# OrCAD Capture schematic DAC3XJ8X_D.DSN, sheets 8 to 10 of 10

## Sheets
8 SHEET 7 - FMC CONN: size B; title: OUTPUT
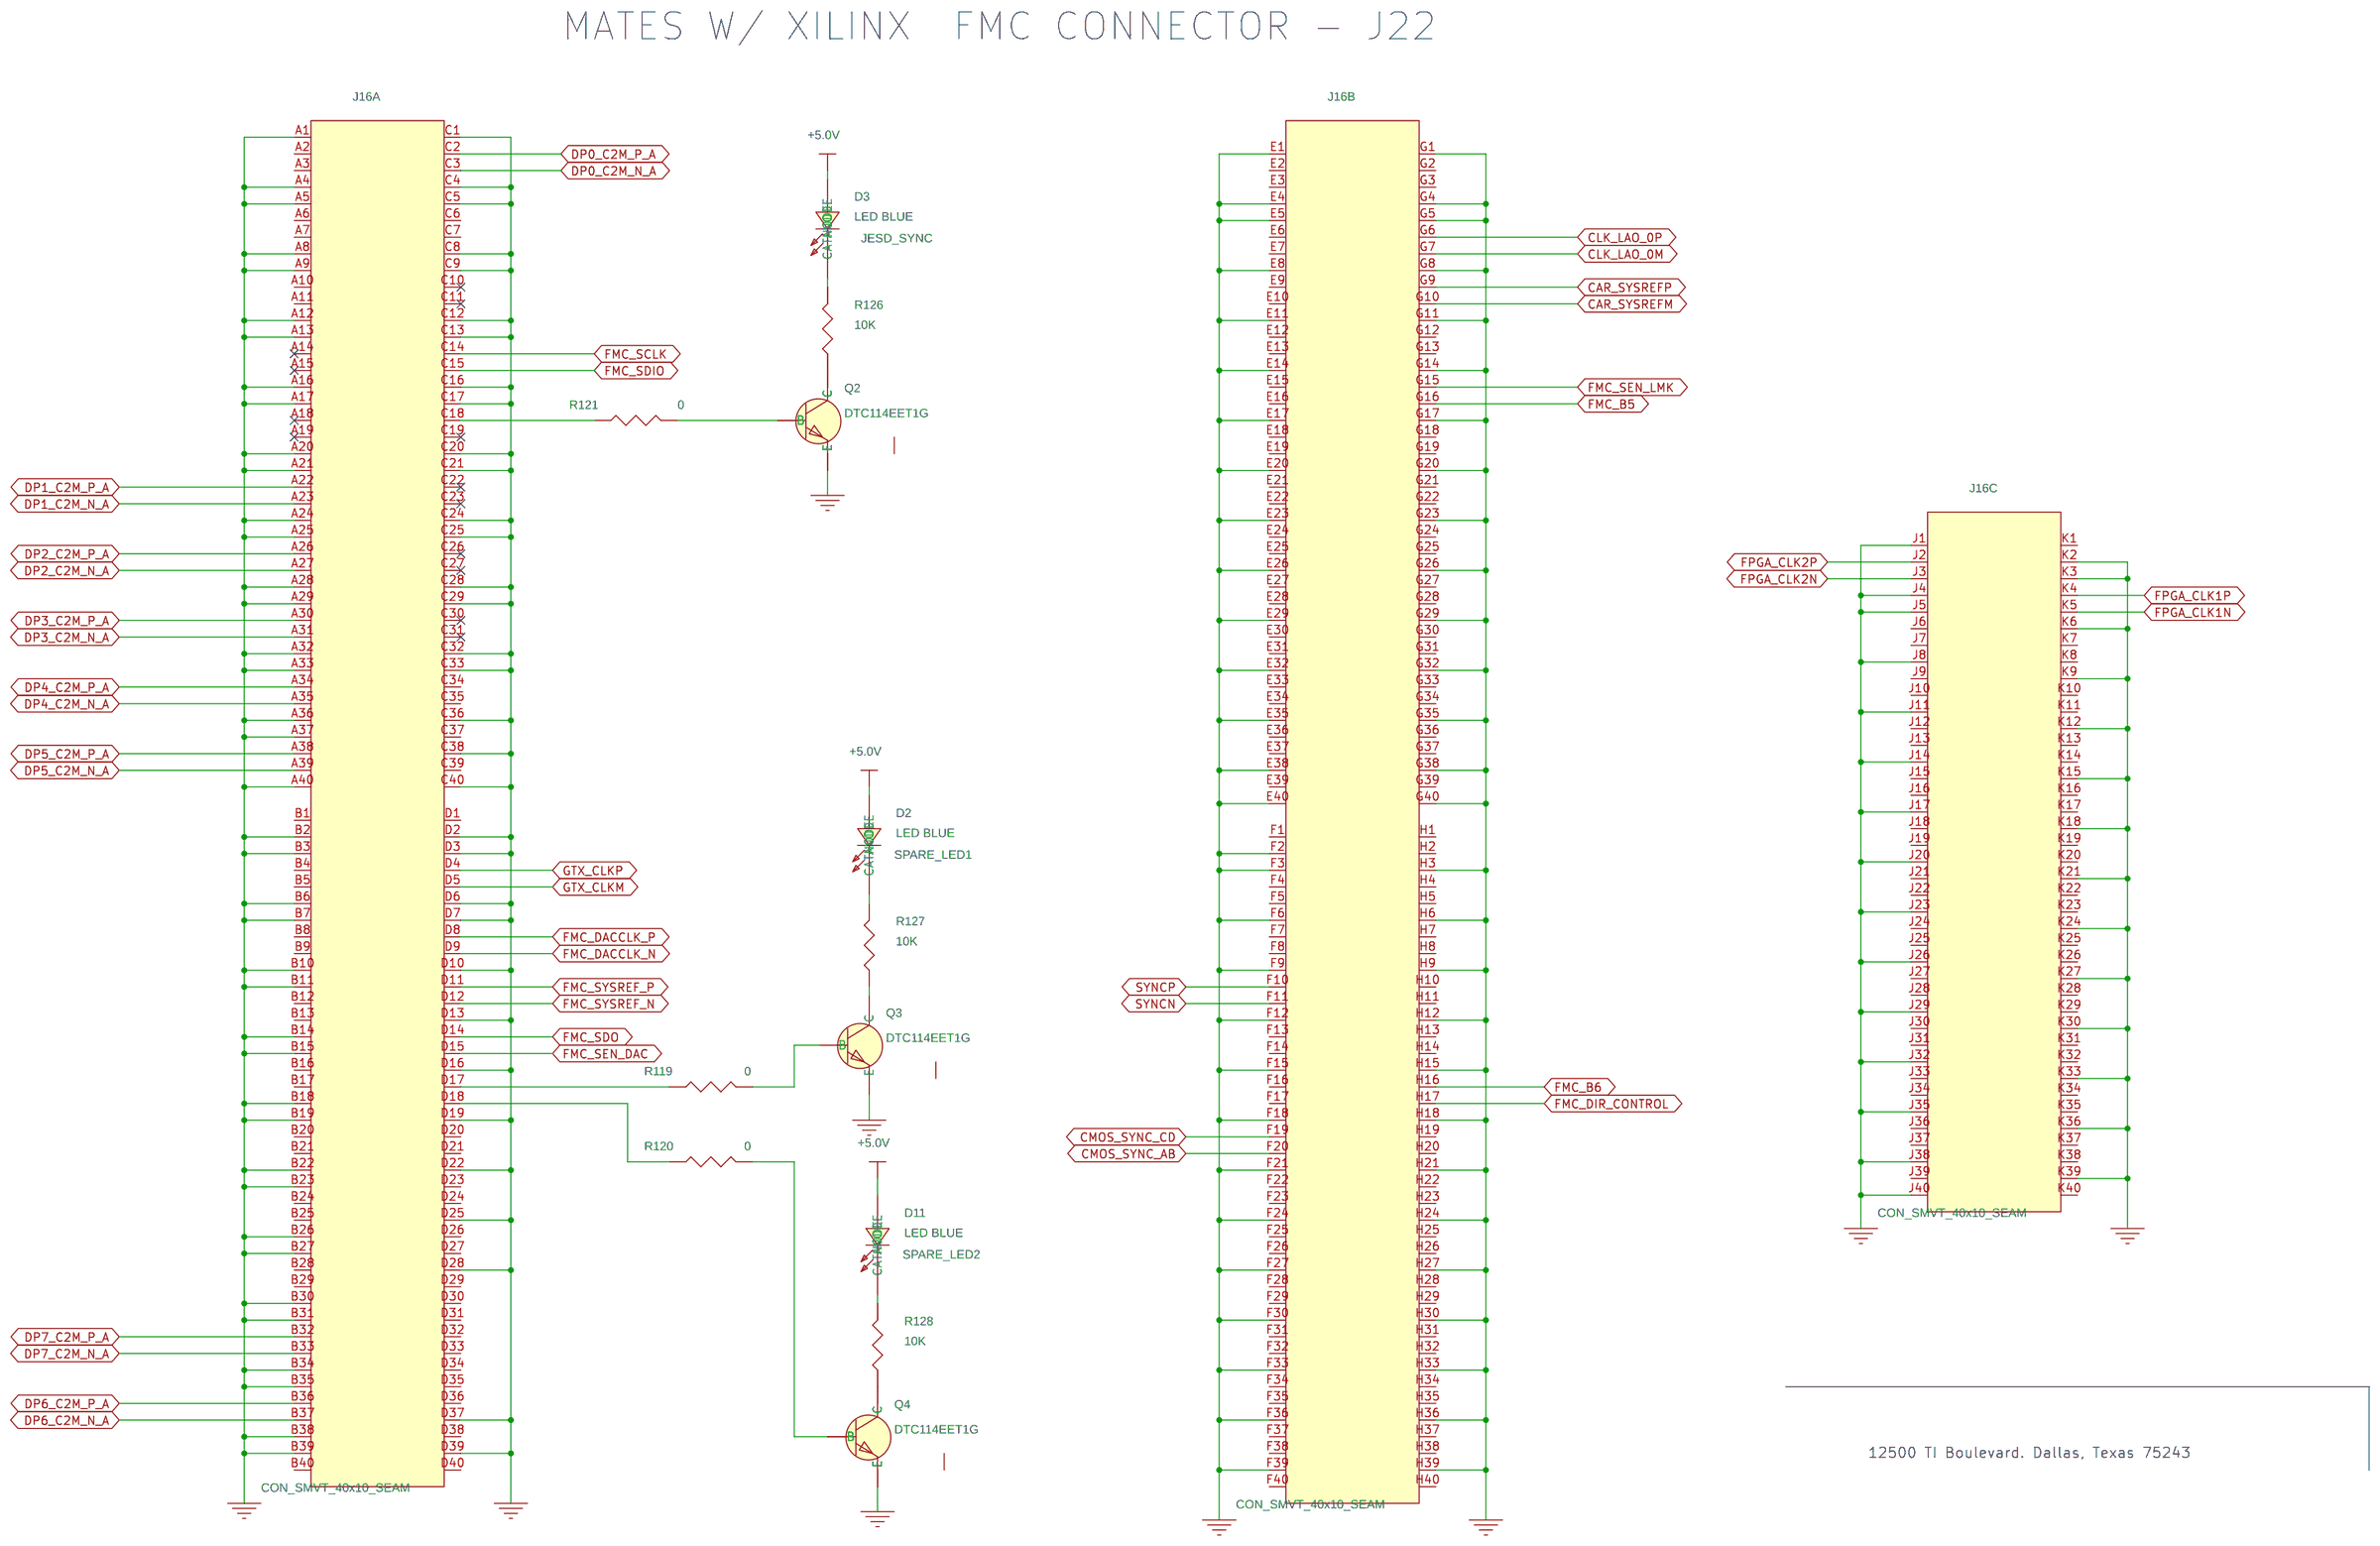
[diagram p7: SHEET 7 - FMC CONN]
9 SHEET 9 - MAIN POWER SUPPLIES: size B; title: MAIN POWER
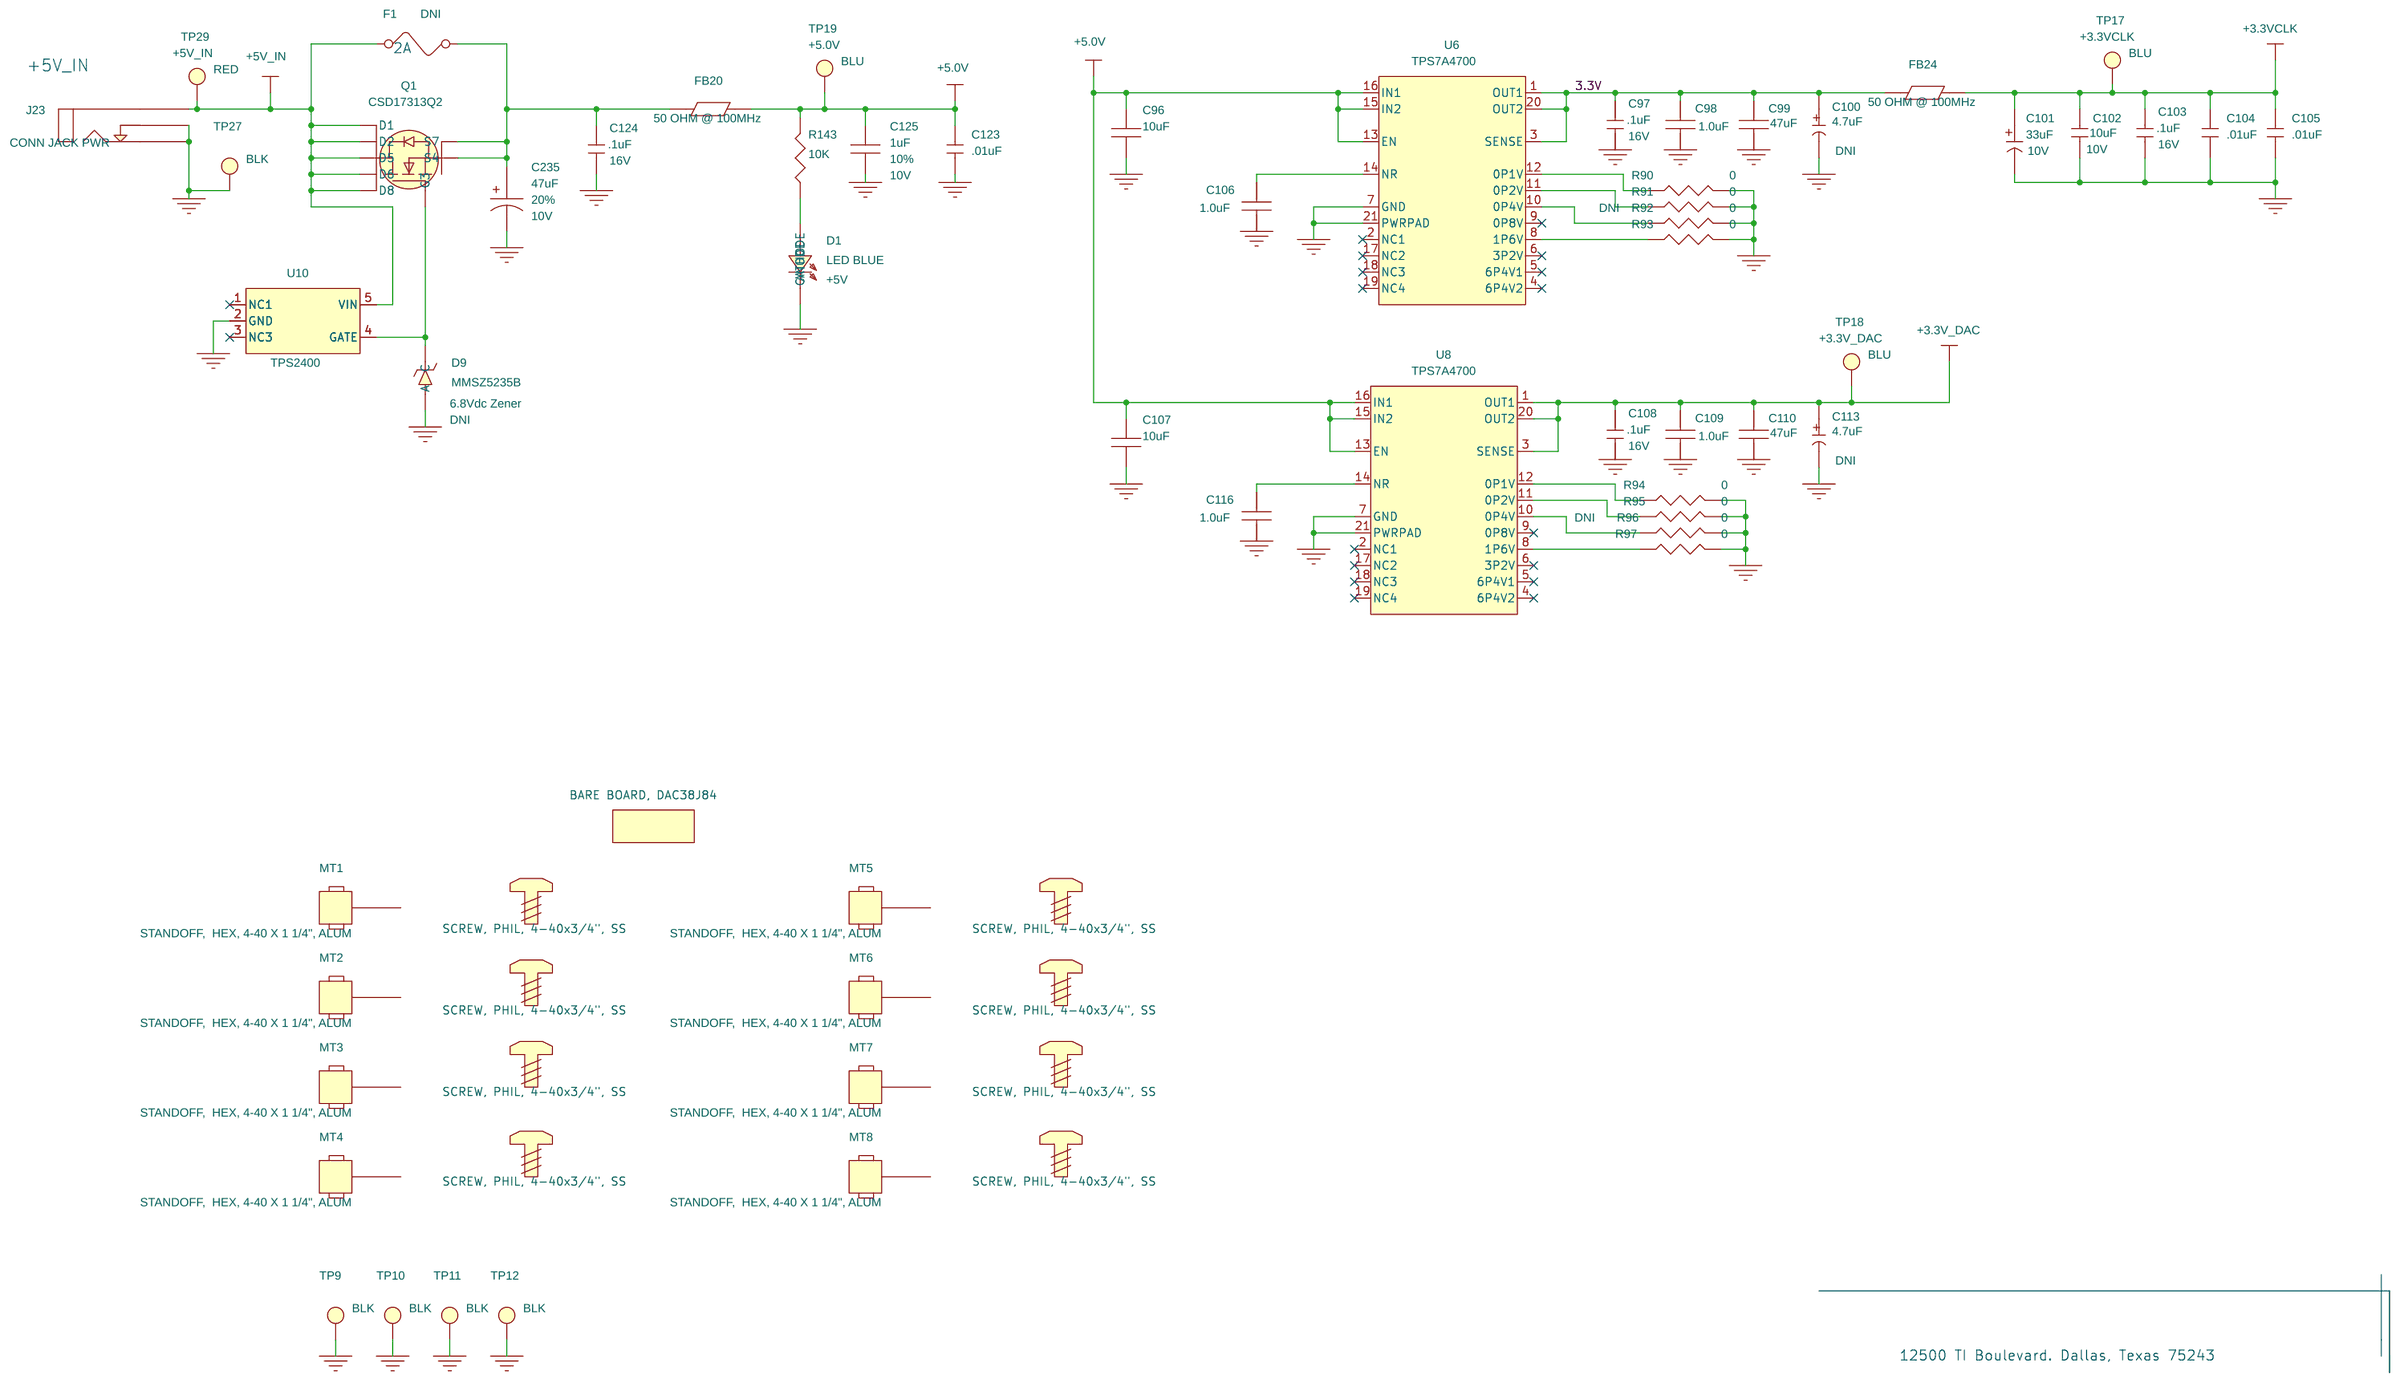
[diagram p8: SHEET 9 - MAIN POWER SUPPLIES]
10 SHEET 8 - USB I/F: size B; title: USB INTERFACE
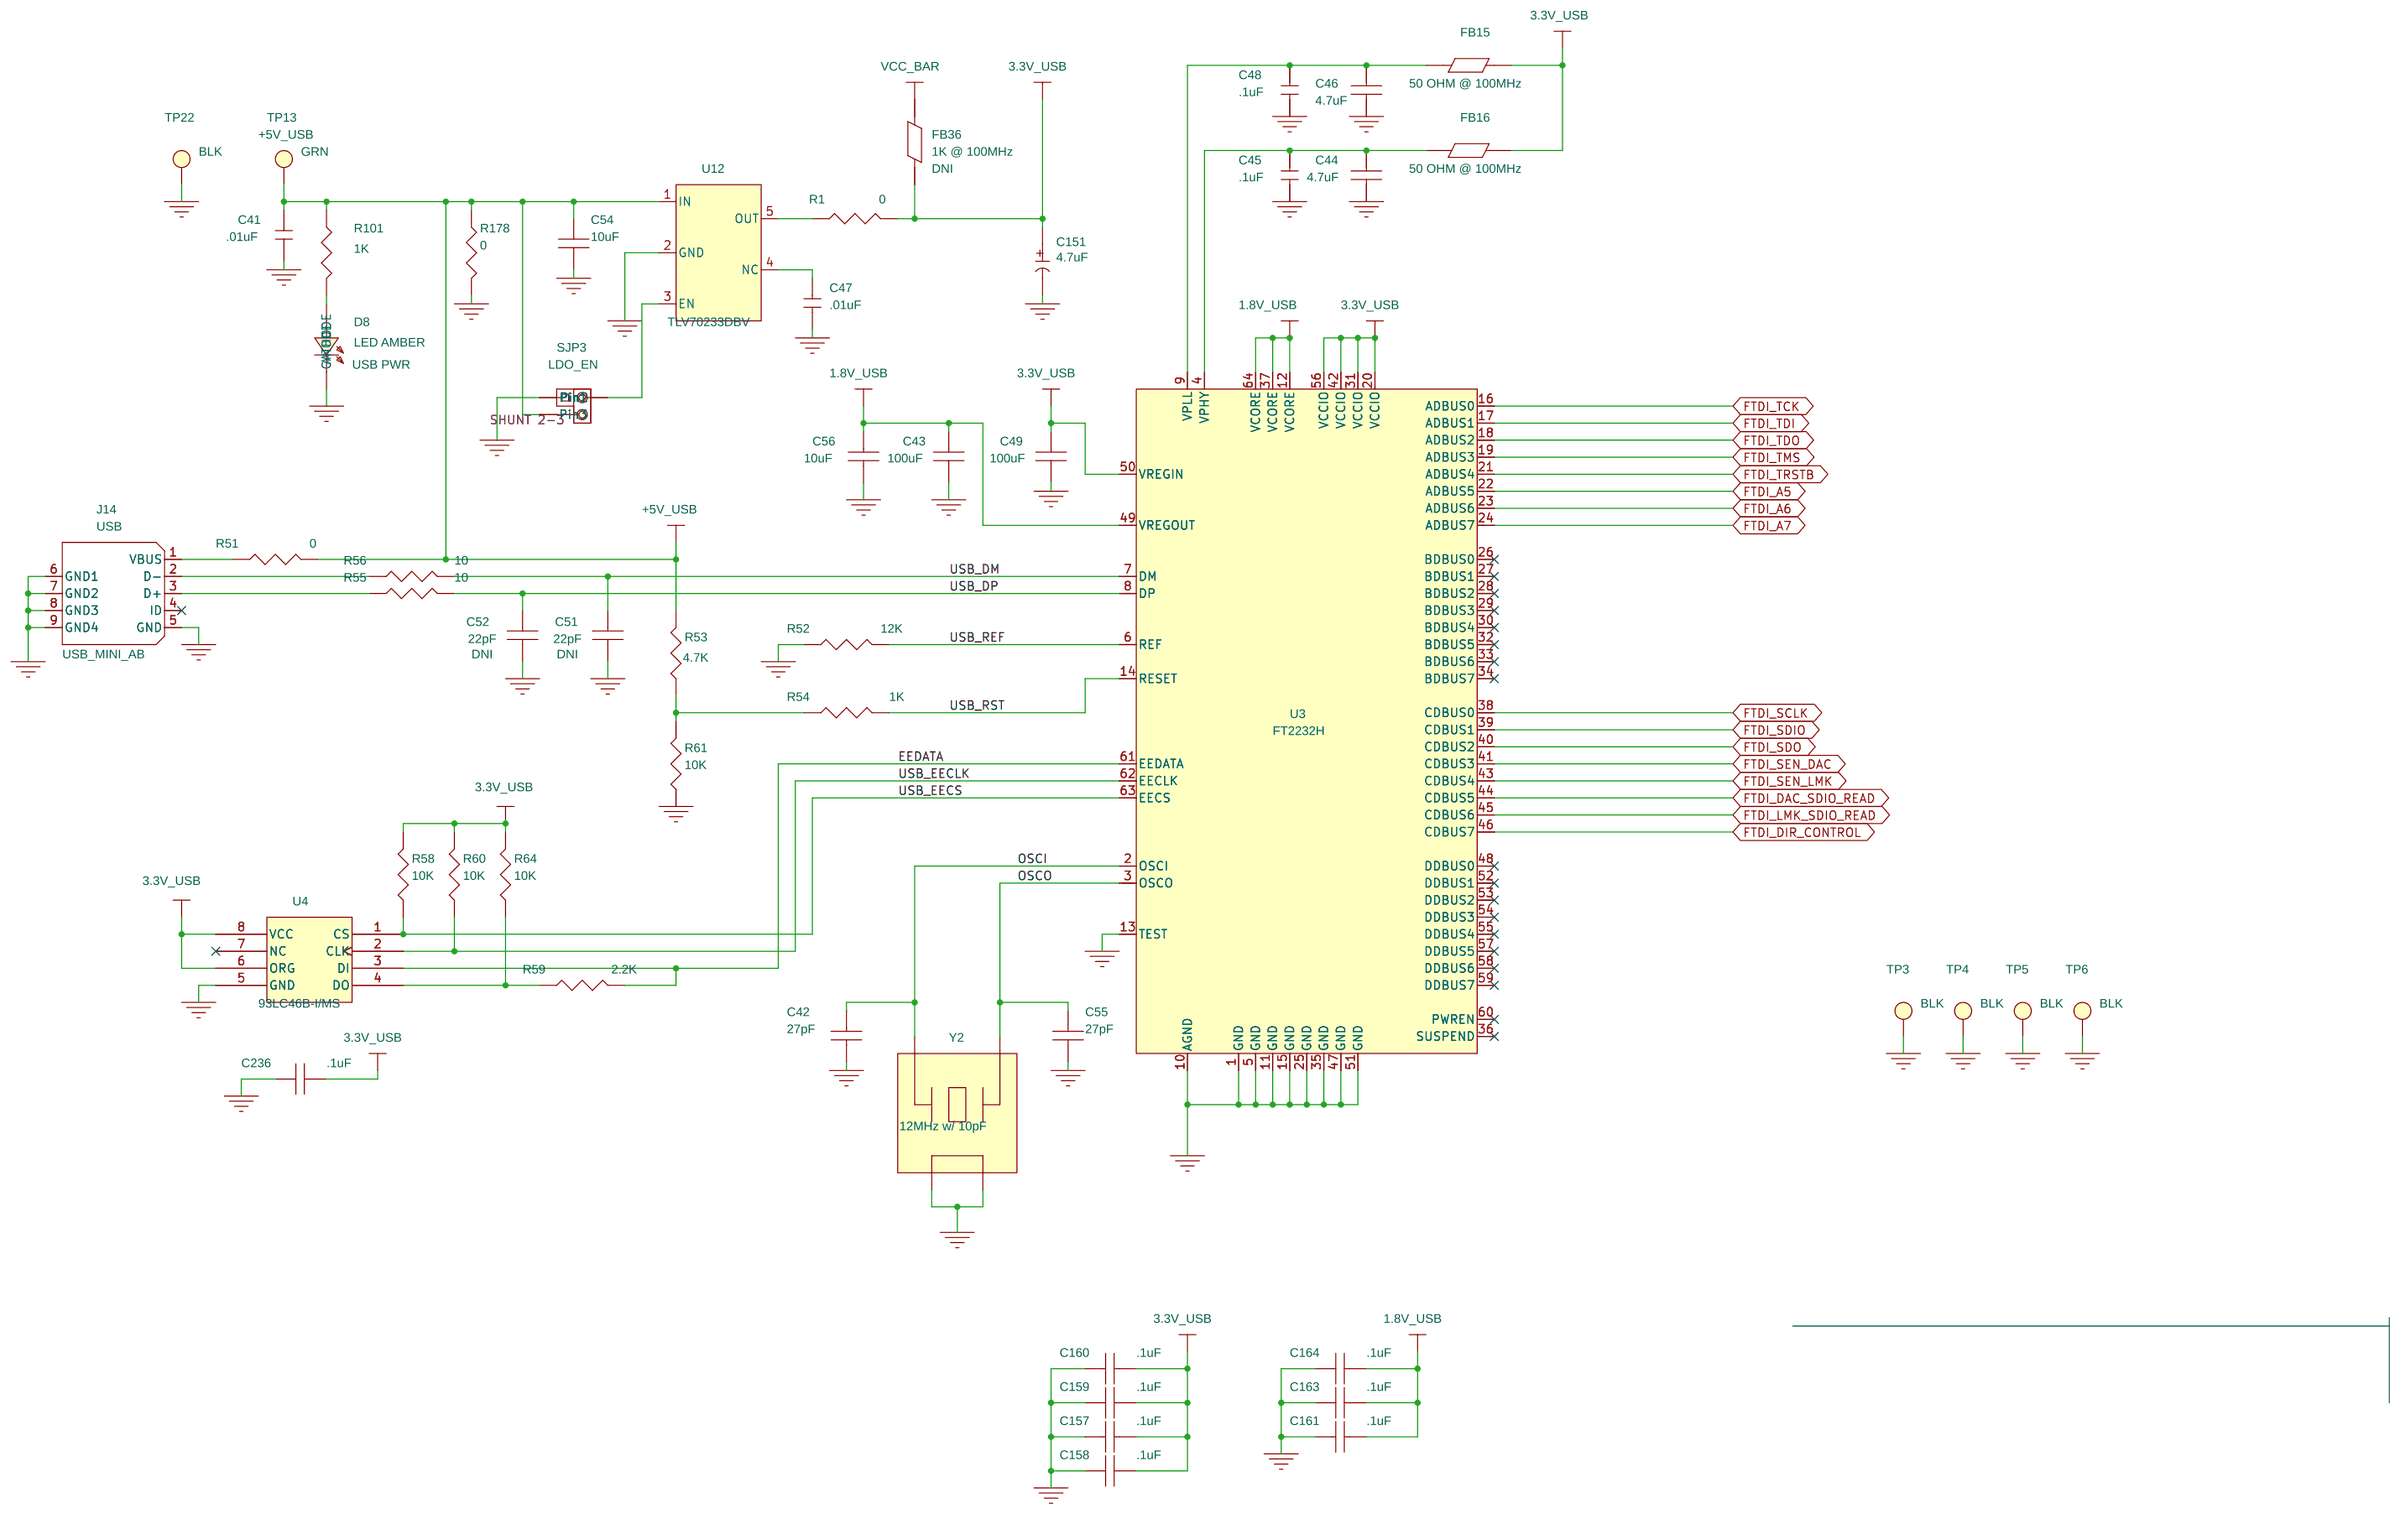
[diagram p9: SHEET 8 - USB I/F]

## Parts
sheet SHEET 7 - FMC CONN
D2  LED BLUE  [LED_1206]
D3  LED BLUE  [LED_1206]
D11  LED BLUE  [LED_1206]
J16  CON_SMVT_40x10_SEAM  [CON_SMVT_40x10_ASP-134487-01]  (sections A,B,C)
Q2  DTC114EET1G  [SOT_416_3_63x31]
Q3  DTC114EET1G  [SOT_416_3_63x31]
Q4  DTC114EET1G  [SOT_416_3_63x31]
R119  0  [0603]
R120  0  [0603]
R121  0  [0603]
R126  10K  [0603]
R127  10K  [0603]
R128  10K  [0603]
sheet SHEET 8 - USB I/F
C41  .01uF  [0603]
C42  27pF  [0402]
C43  100uF  [1206]
C44  4.7uF  [0603]
C45  .1uF  [0402]
C46  4.7uF  [0603]
C47  .01uF  [0603]
C48  .1uF  [0402]
C49  100uF  [1206]
C51  22pF  [0402]
C52  22pF  [0402]
C54  10uF  [1206]
C55  27pF  [0402]
C56  10uF  [1206]
C151  4.7uF  [TANT_B]
C157  .1uF  [0402]
C158  .1uF  [0402]
C159  .1uF  [0402]
C160  .1uF  [0402]
C161  .1uF  [0402]
C163  .1uF  [0402]
C164  .1uF  [0402]
C236  .1uF  [0402]
D8  LED AMBER  [LED_1206]
FB15  50 OHM @ 100MHz  [1206]
FB16  50 OHM @ 100MHz  [1206]
FB36  1K @ 100MHz  [0603]
J14  USB_MINI_AB  [CON_SMRT_USBMNE20_F]
R1  0  [0805]
R51  0  [0603]
R52  12K  [0402]
R53  4.7K  [0402]
R54  1K  [0402]
R55  10  [0402]
R56  10  [0402]
R58  10K  [0402]
R59  2.2K  [0402]
R60  10K  [0402]
R61  10K  [0402]
R64  10K  [0402]
R101  1K  [0402]
R178  0  [0402]
SJP3  JUMPER_L_0603_SMT  [JUMPER_SMD_L_0603]
TP3  BLK  [TP_THVT_100_RND_GND]
TP4  BLK  [TP_THVT_100_RND_GND]
TP5  BLK  [TP_THVT_100_RND_GND]
TP6  BLK  [TP_THVT_100_RND_GND]
TP13  GRN  [TP_THVT_100_RND]
TP22  BLK  [TP_THVT_100_RND_GND]
U3  FT2232H  [LQFP_64_402x402_20]
U4  93LC46B-I/MS  [MSOP_8_118X118_26]
U12  TLV70233DBV  [SOT_5_118X67_57]
Y2  12MHz w/ 10pF  [XTAL_4_SM_130X102]
Z_SH-J9  SHUNT-JUMPER-0603
sheet SHEET 9 - MAIN POWER SUPPLIES
C96  10uF  [0805]
C97  .1uF  [0402]
C98  1.0uF  [0603]
C99  47uF  [1206]
C100  4.7uF  [TANT_B]
C101  33uF  [TANT_B]
C102  10uF  [0805]
C103  .1uF  [0402]
C104  .01uF  [0603]
C105  .01uF  [0603]
C106  1.0uF  [0603]
C107  10uF  [0805]
C108  .1uF  [0402]
C109  1.0uF  [0603]
C110  47uF  [1206]
C113  4.7uF  [TANT_B]
C116  1.0uF  [0603]
C123  .01uF  [0603]
C124  .1uF  [0402]
C125  1uF  [0402]
C235  47uF  [tant_b]
D1  LED BLUE  [LED_1206]
D9  MMSZ5235B  [DIODE_SM_SOD_123]
F1  FUSE 2.0A 63V FAST  [1206]
FB20  50 OHM @ 100MHz  [1206]
FB24  50 OHM @ 100MHz  [1206]
J23  CONN JACK PWR  [CON_RAPC722_JACK_THVT_3]
MT1  STANDOFF,  HEX, 4-40 X 1 1/4", ALUM  [MFG125_PLATED]
MT2  STANDOFF,  HEX, 4-40 X 1 1/4", ALUM  [MFG125_PLATED]
MT3  STANDOFF,  HEX, 4-40 X 1 1/4", ALUM  [MFG125_PLATED]
MT4  STANDOFF,  HEX, 4-40 X 1 1/4", ALUM  [MFG125_PLATED]
MT5  STANDOFF,  HEX, 4-40 X 1 1/4", ALUM  [MFG125_PLATED]
MT6  STANDOFF,  HEX, 4-40 X 1 1/4", ALUM  [MFG125_PLATED]
MT7  STANDOFF,  HEX, 4-40 X 1 1/4", ALUM  [MFG125_PLATED]
MT8  STANDOFF,  HEX, 4-40 X 1 1/4", ALUM  [MFG125_PLATED]
Q1  CSD17313Q2  [mosfet_8_2mmx2mm_0p65]
R90  0  [0402]
R91  0  [0402]
R92  0  [0402]
R93  0  [0402]
R94  0  [0402]
R95  0  [0402]
R96  0  [0402]
R97  0  [0402]
R143  10K  [0603]
TP9  BLK  [TP_THVT_100_RND_GND]
TP10  BLK  [TP_THVT_100_RND_GND]
TP11  BLK  [TP_THVT_100_RND_GND]
TP12  BLK  [TP_THVT_100_RND_GND]
TP17  BLU  [TP_THVT_100_RND]
TP18  BLU  [TP_THVT_100_RND]
TP19  BLU  [TP_THVT_100_RND]
TP27  BLK  [TP_THVT_100_RND_GND]
TP29  RED  [TP_THVT_100_RND]
U6  TPS7A4700  [qfn20_rgw_p65pitch]
U8  TPS7A4700  [qfn20_rgw_p65pitch]
U10  TPS2400  [DBV5]
Z_BOARD1  BARE BOARD, DAC38J84
Z_SCREW1  SCREW, PHIL, 4-40x3/4", SS
Z_SCREW2  SCREW, PHIL, 4-40x3/4", SS
Z_SCREW3  SCREW, PHIL, 4-40x3/4", SS
Z_SCREW4  SCREW, PHIL, 4-40x3/4", SS
Z_SCREW5  SCREW, PHIL, 4-40x3/4", SS
Z_SCREW6  SCREW, PHIL, 4-40x3/4", SS
Z_SCREW7  SCREW, PHIL, 4-40x3/4", SS
Z_SCREW8  SCREW, PHIL, 4-40x3/4", SS

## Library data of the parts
D2 = LED: CLASS: DISCRETE; Mfr_Name: LITE ON; Mfr_Part_Number: LTST-C150TBKT; TI_SILKTEXT: SPARE_LED1
D3 = LED: CLASS: DISCRETE; Mfr_Name: LITE ON; Mfr_Part_Number: LTST-C150TBKT; TI_SILKTEXT: JESD_SYNC
D11 = LED: CLASS: DISCRETE; Mfr_Name: LITE ON; Mfr_Part_Number: LTST-C150TBKT; TI_SILKTEXT: SPARE_LED2
J16 = CON_SMVT_40X10_ASP-134487-01: Mfr_Part_Number: SEAM-40-02.0-S-10-2-A-K-TR
Q2-Q4 = MMBT2222A: Mfr_Name: ON Semiconductor
R119-R121 = Res_0603_Zero_H
R126-R128 = R: Mfr_Name: PANASONIC; Mfr_Part_Number: ERJ-3EKF1002V; TOL: 1%; VOLTAGE: 1/10W
C41 C47 C104 C105 C123 = CAP_0603_0.01uF: Mfr_Part_Number: C0603C103K5RACTU
C42 C55 = CAP_NP: GROUP: NOT INSTALLED; Mfr_Name: YAGEO; Mfr_Part_Number: CC0402JRNPO9BN270; PART_NUMBER: GRM1885C2A330JA01D; TOL: 5%; VOLTAGE: 50V
C43 C49 = CAP_1206: Mfr_Name: KEMET; Mfr_Part_Number: C1206C107M9PACTU
C44 C46 = CAP_NP_0: Mfr_Name: Kemet; Mfr_Part_Number: C0603C475K8PACTU; TOL: 10%; VOLTAGE: 10V
C45 C48 C97 C103 C108 C124 = CAP0603: Mfr_Name: MURATA; Mfr_Part_Number: GRM155R71C104KA88D; TOL: 10%; Voltage: 16V
C51 C52 = CAP_NP: Mfr_Name: AVX; Mfr_Part_Number: 04025A220KAT2A_DNI; Note: DNI; TOL: 10%; VOLTAGE: 50V
C54 C56 = CAP_NP_1: CLASS: DISCRETE; Mfr_Name: MURATA; Mfr_Part_Number: GRM31CR61E106KA12L; TOL: 10%; VOLTAGE: 16V
C151 = CAP_TANT_B_4.7uF_10V: Mfr_Part_Number: TAJB475K010RNJ
C157-C161 C163 C164 C236 = CAPACITOR_NP_1: Mfr_Name: MURATA; Mfr_Part_Number: GRM155R71C104KA88D; TOL: 10%; Voltage: 16V
D8 = LED_AMBER_1206: TI_SILKTEXT: USB PWR
FB15 FB16 FB20 FB24 = FERRITE_BEAD: Mfr_Name: MURATA; Mfr_Part_Number: BLM31PG500SN1
FB36 = FERRITE_BEAD: Mfr_Name: TAIYO YUDEN; Mfr_Part_Number: BLM21AG102SN1D_DNI; Note: DNI
J14 = USB_MINI_AB_MNE20-5G5P10: Manufacturer: WURTH ELEKTRONIK; Manufacturer Part Number: 651 305 142 821; Mfr_Name: WURTH ELEKTRONIK; Mfr_Part_Number: 651 305 142 821; TI_SILKTEXT: USB
R1 = Res_0805_Zero_H
R51 = Res_0402_Zero: Mfr_Name: PANASONIC; Mfr_Part_Number: ERJ-3GEY0R00V
R52 = R: Mfr_Name: PANASONIC; Mfr_Part_Number: ERJ-2RKF1202X; TOL: 1%; Wattage: 1/16W
R53 = RESISTOR: 10K ohm, +/-1%, 1/16W(0402); Mfr_Name: PANASONIC; Mfr_Part_Number: ERJ-2RKF4701X; Package: SMD; Terasic_Prt: M0597; Type: Resistor
R54 = R_0: Mfr_Name: PANASONIC; Mfr_Part_Number: ERJ-2RKF1001X; PART_NUMBER: Panasonic ERJ-2RKF1001X; TOL: 1%
R55 R56 = Res_0402_10_H
R58 R60 R61 R64 = R_0: CLASS: DISCRETE; Mfr_Name: PANASONIC; Mfr_Part_Number: ERJ-2RKF1002X; TOL: 1%
R59 = RESISTOR: 2.2K ohm, +/-1%, 1/16W(0402); Mfr_Name: Yageo; Mfr_Part_Number: RC0402FR-072K2L; Package: SMD; Terasic_Prt: M0733; Type: Resistor
R101 = R: Mfr_Name: PANASONIC; Mfr_Part_Number: ERJ-2RKF1001X; TOL: 5%; VOLTAGE: 1/16W
R178 = Res_0402_Zero_DNI
SJP3 = JUMPER_SMD_L_0603: TI_Silktext: LDO_EN
TP3-TP6 TP9-TP12 TP22 TP27 = TESTPOINT_BLK
TP13 = TESTPOINT_GRN: TI_SILKTEXT: +5V_USB
U3 = FT4232H_2: Mfr_Part_Number: FT2232HQ-REEL
U4 = EEPROM: 93LC46B-I/SN,Serial EEPROM, 64 x 16bit, 2.5V-5.5V; Mfr_Name: Microchip; Package: SMD; Terasic_Prt: M0252
U12 = TLV702XX-SOT23_0: Mfr_Part_Number: TLV70233DBVT
Y2 = CRYSTAL1-4_SM: Mfr_Name: Abracon; Mfr_Part_Number: ABM8G-12.000MHZ-B4Y-T
Z_SH-J9 = SHUNT-JUMPER-0603: TI_SILK: SHUNT 2-3
C96 C107 = CAP_NP_1: CLASS: DISCRETE; Mfr_Name: MURATA; Mfr_Part_Number: GRM21BR71A106KE51L; TOL: 10%; VOLTAGE: 10V
C98 C106 C109 C116 = CAP_NP_0: Mfr_Name: YAGEO; Mfr_Part_Number: CC0603KRX7R7BB105; TOL: 10%; VOLTAGE: 16V
C99 C110 = CAP_NP_0: Mfr_Name: MURATA; Mfr_Part_Number: GRM31CR61A476ME15L; TOL: 20%; VOLTAGE: 10V
C100 C113 = CAP_TANT_B_4.7uF_10V: Mfr_Part_Number: TAJB475K010RNJ_DNI; Note: DNI
C101 = CAP_POL-B: Mfr_Name: AVX; Mfr_Part_Number: TPSB336K016R0350; TOL: 10%; Voltage: 10V
C102 = CAP0201: CLASS: DISCRETE; Mfr_Name: MURATA; Mfr_Part_Number: GRM21BR71A106KE51L; TOL: 10%; VOLTAGE: 10V
C125 = CAPACITOR_NP_1: Mfr_Name: MURATA; Mfr_Part_Number: GRM155R61A105KE15D; TOL: 10%; Voltage: 10V
C235 = CAP_POL: Mfr_Name: Kemet; Mfr_Part_Number: T491B476M010AT; TOL: 20%; VOLTAGE: 10V
D1 = LED_BLUE_1206: TI_SILKTEXT: +5V
D9 = DIODE_MMSZ5235B: Mfr_Part_Number: MMSZ5235B_DNI; Note: DNI; Voltage: 6.8Vdc Zener
F1 = FUSE_0: Mfr_Name: TE Connectivity; Mfr_Part_Number: 1206SFF200F/63-2_DNI; Note: DNI
J23 = CONN_JACK_PWR: Mfr_Name: Switchcraft; Mfr_Part_Number: RAPC722X; Part Number: RAPC722
MT1-MT8 = MOUNTING_HOLE: Mfr_Name: RAF ELECTRONIC HARDWARE; Mfr_Part_Number: 2116-440-AL-7; Note: OR EQUIVALENT
Q1 = PWR_MOSFET_CSD17313Q2: Mfr_Name: Texas Instruments
R90 R91 R93-R95 R97 = R: Mfr_Name: PANASONIC; Mfr_Part_Number: ERJ-2GE0R00X; TOL: 5%
R92 R96 = R: Mfr_Name: PANASONIC; Mfr_Part_Number: ERJ-2GE0R00X_DNI; Note: DNI; TOL: 5%
R143 = RES0603: Mfr_Name: PANASONIC; Mfr_Part_Number: ERJ-3EKF1002V; TOL: 1%; Wattage: 1/10W
TP17 = TESTPOINT_BLUE: TI_SILKTEXT: +3.3VCLK
TP18 = TESTPOINT_BLUE: TI_SILKTEXT: +3.3V_DAC
TP19 = TESTPOINT_BLUE: TI_SILKTEXT: +5.0V
TP29 = TESTPOINT_RED: TI_SILKTEXT: +5V_IN
U6 U8 = TPS7A4700: Mfr_Name: Texas Instruments; Mfr_Part_Number: TPS7A4700RGWT
U10 = TPS2400: Mfr_Name: Texas Instruments; Mfr_Part_Number: TPS2400DBVT
Z_BOARD1 = BARE_BOARD: Mfr_Name: VIASYSTEMS; Mfr_Part_Number: DAC38J84 REV C
Z_SCREW1-Z_SCREW8 = STANDOFF-SCREW: Mfr_Part_Number: PMSSS 440 0075 PH

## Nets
1.8V_USB: C43.1 C56.1 C161.2 C163.2 C164.2 U3.12(VCORE) U3.37(VCORE) U3.49(VREGOUT) U3.64(VCORE) ; also on sheet 5
3.3V: C97.1 C98.1 C99.1 C100.1 FB24.2 U6.1(OUT1) U6.3(SENSE) U6.20(OUT2)
3.3V_USB: C49.1 C151.1 C157.2 C158.2 C159.2 C160.2 C236.2 FB15.1 FB16.1 FB36.2 R1.2 R58.2 R60.2 R64.2 U3.20(VCCIO) U3.31(VCCIO) U3.42(VCCIO) U3.50(VREGIN) U3.56(VCCIO) U4.6(ORG) U4.8(VCC) ; also on sheet 5
+3.3V_DAC: C108.1 C109.1 C110.1 C113.1 TP18.1(TP) U8.1(OUT1) U8.3(SENSE) U8.20(OUT2) ; also on sheet 2 3
+3.3VCLK: C101.1 C102.1 C103.1 C104.1 C105.1 FB24.1 FB36.1 TP17.1(TP) ; also on sheet 5 6
+5.0V: C96.1 C107.1 C123.1 C125.1 D2.1(ANODE) D3.1(ANODE) D11.1(ANODE) FB20.1 R143.2 TP19.1(TP) U6.13(EN) U6.15(IN2) U6.16(IN1) U8.13(EN) U8.15(IN2) U8.16(IN1) ; also on sheet 2
+5V_IN: F1.1 J23.1 Q1.1(D1) Q1.2(D2) Q1.5(D5) Q1.6(D6) Q1.8(D8) TP29.1(TP) U10.5(VIN)
+5V_USB: C41.1 C54.1 R51.1 R53.1 R101.1 R178.1 SJP3.3(Pin3) TP13.1(TP) U12.1(IN)
GND: C41.2 C42.2 C43.2 C44.2 C45.2 C46.2 C47.2 C48.2 C49.2 C51.2 C52.2 C54.2 C55.2 C56.2 C96.2 C97.2 C98.2 C99.2 C100.2 C101.2 C102.2 C103.2 C104.2 C105.2 C106.2 C107.2 C108.2 C109.2 C110.2 C113.2 C116.2 C123.2 C124.2 C125.2 C151.2 C157.1 C158.1 C159.1 C160.1 C161.1 C163.1 C164.1 C235.2 C236.1 D1.2(CATHODE) D8.2(CATHODE) D9.1(A) J14.5(GND) J14.6(GND1) J14.7(GND2) J14.8(GND3) J14.9(GND4) J16.A1 J16.A4 J16.A5 J16.A8 J16.A9 J16.A12 J16.A13 J16.A16 J16.A17 J16.A20 J16.A21 J16.A24 J16.A25 J16.A28 J16.A29 J16.A32 J16.A33 J16.A36 J16.A37 J16.A40 J16.B2 J16.B3 J16.B6 J16.B7 J16.B10 J16.B11 J16.B14 J16.B15 J16.B18 J16.B19 J16.B22 J16.B23 J16.B26 J16.B27 J16.B30 J16.B31 J16.B34 J16.B35 J16.B38 J16.B39 J16.C1 J16.C4 J16.C5 J16.C8 J16.C9 J16.C12 J16.C13 J16.C16 J16.C17 J16.C20 J16.C21 J16.C24 J16.C25 J16.C28 J16.C29 J16.C32 J16.C33 J16.C36 J16.C38 J16.C40 J16.D2 J16.D3 J16.D6 J16.D7 J16.D10 J16.D13 J16.D16 J16.D19 J16.D22 J16.D25 J16.D28 J16.D37 J16.D39 J16.E1 J16.E4 J16.E5 J16.E8 J16.E11 J16.E14 J16.E17 J16.E20 J16.E23 J16.E26 J16.E29 J16.E32 J16.E35 J16.E38 J16.E40 J16.F2 J16.F3 J16.F6 J16.F9 J16.F12 J16.F15 J16.F18 J16.F21 J16.F24 J16.F27 J16.F30 J16.F33 J16.F36 J16.F39 J16.G1 J16.G4 J16.G5 J16.G8 J16.G11 J16.G14 J16.G17 J16.G20 J16.G23 J16.G26 J16.G29 J16.G32 J16.G35 J16.G38 J16.G40 J16.H3 J16.H6 J16.H9 J16.H12 J16.H15 J16.H18 J16.H21 J16.H24 J16.H27 J16.H30 J16.H33 J16.H36 J16.H39 J16.J1 J16.J4 J16.J5 J16.J8 J16.J11 J16.J14 J16.J17 J16.J20 J16.J23 J16.J26 J16.J29 J16.J32 J16.J35 J16.J38 J16.J40 J16.K2 J16.K3 J16.K6 J16.K9 J16.K12 J16.K15 J16.K18 J16.K21 J16.K24 J16.K27 J16.K30 J16.K33 J16.K36 J16.K39 J23.2 J23.3 Q2.2(E) Q3.2(E) Q4.2(E) R52.2 R61.1 R90.1 R91.1 R92.1 R93.1 R94.1 R95.1 R96.1 R97.1 R178.2 SJP3.1(Pin1) TP3.1(TP) TP4.1(TP) TP5.1(TP) TP6.1(TP) TP9.1(TP) TP10.1(TP) TP11.1(TP) TP12.1(TP) TP22.1(TP) TP27.1(TP) U3.1(GND) U3.5(GND) U3.10(AGND) U3.11(GND) U3.13(TEST) U3.15(GND) U3.25(GND) U3.35(GND) U3.47(GND) U3.51(GND) U4.5(GND) U6.7(GND) U6.21(PWRPAD) U8.7(GND) U8.21(PWRPAD) U10.2(GND) U12.2(GND) Y2.2 Y2.4 ; also on sheet 2 3 4 5 6 7
CAR_SYSREFM: J16.G10 ; also on sheet 6
CAR_SYSREFP: J16.G9 ; also on sheet 6
CLK_LAO_0M: J16.G7 ; also on sheet 6
CLK_LAO_0P: J16.G6 ; also on sheet 6
CMOS_SYNC_AB: J16.F20 ; also on sheet 7
CMOS_SYNC_CD: J16.F19 ; also on sheet 7
DP0_C2M_N_A: J16.C3 ; also on sheet 7
DP0_C2M_P_A: J16.C2 ; also on sheet 7
DP1_C2M_N_A: J16.A23 ; also on sheet 7
DP1_C2M_P_A: J16.A22 ; also on sheet 7
DP2_C2M_N_A: J16.A27 ; also on sheet 7
DP2_C2M_P_A: J16.A26 ; also on sheet 7
DP3_C2M_N_A: J16.A31 ; also on sheet 7
DP3_C2M_P_A: J16.A30 ; also on sheet 7
DP4_C2M_N_A: J16.A35 ; also on sheet 7
DP4_C2M_P_A: J16.A34 ; also on sheet 7
DP5_C2M_N_A: J16.A39 ; also on sheet 7
DP5_C2M_P_A: J16.A38 ; also on sheet 7
DP6_C2M_N_A: J16.B37 ; also on sheet 7
DP6_C2M_P_A: J16.B36 ; also on sheet 7
DP7_C2M_N_A: J16.B33 ; also on sheet 7
DP7_C2M_P_A: J16.B32 ; also on sheet 7
EEDATA: R59.1 U3.61(EEDATA) U4.3(DI)
FMC_B5: J16.G16 ; also on sheet 5
FMC_B6: J16.H16 ; also on sheet 5
FMC_DACCLK_N: J16.D9 ; also on sheet 7
FMC_DACCLK_P: J16.D8 ; also on sheet 7
FMC_DIR_CONTROL: J16.H17 ; also on sheet 5
FMC_SCLK: J16.C14 ; also on sheet 5
FMC_SDIO: J16.C15 ; also on sheet 5
FMC_SDO: J16.D14 ; also on sheet 5
FMC_SEN_DAC: J16.D15 ; also on sheet 5
FMC_SEN_LMK: J16.G15 ; also on sheet 5
FMC_SYSREF_N: J16.D12 ; also on sheet 7
FMC_SYSREF_P: J16.D11 ; also on sheet 7
FPGA_CLK1N: J16.K5 ; also on sheet 2
FPGA_CLK1P: J16.K4 ; also on sheet 2
FPGA_CLK2N: J16.J3 ; also on sheet 2
FPGA_CLK2P: J16.J2 ; also on sheet 2
FTDI_A5: U3.22(ADBUS5) ; also on sheet 5
FTDI_A6: U3.23(ADBUS6) ; also on sheet 5
FTDI_A7: U3.24(ADBUS7) ; also on sheet 5
FTDI_DAC_SDIO_READ: U3.44(CDBUS5) ; also on sheet 5
FTDI_DIR_CONTROL: U3.46(CDBUS7) ; also on sheet 5
FTDI_LMK_SDIO_READ: U3.45(CDBUS6) ; also on sheet 5
FTDI_SCLK: U3.38(CDBUS0) ; also on sheet 5
FTDI_SDIO: U3.39(CDBUS1) ; also on sheet 5
FTDI_SDO: U3.40(CDBUS2) ; also on sheet 5
FTDI_SEN_DAC: U3.41(CDBUS3) ; also on sheet 5
FTDI_SEN_LMK: U3.43(CDBUS4) ; also on sheet 5
FTDI_TCK: U3.16(ADBUS0) ; also on sheet 5
FTDI_TDI: U3.17(ADBUS1) ; also on sheet 5
FTDI_TDO: U3.18(ADBUS2) ; also on sheet 5
FTDI_TMS: U3.19(ADBUS3) ; also on sheet 5
FTDI_TRSTB: U3.21(ADBUS4) ; also on sheet 5
GTX_CLKM: J16.D5 ; also on sheet 6
GTX_CLKP: J16.D4 ; also on sheet 6
OSCI: C42.1 U3.2(OSCI) Y2.1
OSCO: C55.1 U3.3(OSCO) Y2.3
SYNCN: J16.F11 ; also on sheet 7
SYNCP: J16.F10 ; also on sheet 7
USB_DM: C51.1 R56.2 U3.7(DM)
USB_DP: C52.1 R55.2 U3.8(DP)
USB_EECLK: R60.1 U3.62(EECLK) U4.2(CLK)
USB_EECS: R58.1 U3.63(EECS) U4.1(CS)
USB_REF: R52.1 U3.6(REF)
USB_RST: R54.2 U3.14(RESET)
N16791695: C47.1 U12.4(NC)
N16791764: J14.1(VBUS) R51.2
N16791900: C44.1 C45.1 FB16.2 U3.4(VPHY)
N16791904: C46.1 C48.1 FB15.2 U3.9(VPLL)
N16792038: J14.3(D+) R55.1
N16792040: J14.2(D-) R56.1
N16792068: R53.2 R54.1 R61.2
N16792392: R59.2 R64.1 U4.4(DO)
N16960291: C124.1 C235.1 F1.2 FB20.2 Q1.4(S4) Q1.7(S7)
N16960299: D9.2(C) Q1.3(G3) U10.4(GATE)
N17033325: D8.1(ANODE) R101.2
N17201332: D1.1(ANODE) R143.1
N17211055: R1.1 U12.5(OUT)
N17267622: SJP3.2(Pin2) U12.3(EN)
N17273566: Q3.1(B) R119.2
N17273570: Q4.1(B) R120.2
N17273576: J16.D18 R120.1
N17273599: J16.D17 R119.1
N17274139: Q3.3(C) R127.2
N17274205: Q2.1(B) R121.2
N17277740: D2.2(CATHODE) R127.1
N17277758: D3.2(CATHODE) R126.1
N17277849: D11.2(CATHODE) R128.1
N17332981: Q2.3(C) R126.2
N17332982: Q4.3(C) R128.2
N18118787: C106.1 U6.14(NR)
N18494750: R91.2 U6.11(0P2V)
N18494760: R90.2 U6.12(0P1V)
N18496347: R92.2 U6.10(0P4V)
N18497261: R93.2 U6.8(1P6V)
N18499997: C116.1 U8.14(NR)
N18501914: R97.2 U8.8(1P6V)
N18501918: R95.2 U8.11(0P2V)
N18501920: R94.2 U8.12(0P1V)
N18501930: R96.2 U8.10(0P4V)
N18529139: J16.C18 R121.1

Not connected (* = marked no-connect by the designer): J14 4(ID)*; J16 A2 A3 A6 A7 A10 A11 A14* A15* A18* A19* B1 B4 B5 B8 B9 B12 B13 B16 B17 B20 B21 B24 B25 B28 B29 B40 C6 C7 C10* C11* C19* C22* C23* C26* C27* C30* C31* C34 C35 C37 C39 D1 D20 D21 D23 D24 D26 D27 D29 D30 D31 D32 D33 D34 D35 D36 D38 D40 E2 E3 E6 E7 E9 E10 E12 E13 E15 E16 E18 E19 E21 E22 E24 E25 E27 E28 E30 E31 E33 E34 E36 E37 E39 F1 F4 F5 F7 F8 F13 F14 F16 F17 F22 F23 F25 F26 F28 F29 F31 F32 F34 F35 F37 F38 F40 G2 G3 G12 G13 G18 G19 G21 G22 G24 G25 G27 G28 G30 G31 G33 G34 G36 G37 G39 H1 H2 H4 H5 H7 H8 H10 H11 H13 H14 H19 H20 H22 H23 H25 H26 H28 H29 H31 H32 H34 H35 H37 H38 H40 J6 J7 J9 J10 J12 J13 J15 J16 J18 J19 J21 J22 J24 J25 J27 J28 J30 J31 J33 J34 J36 J37 J39 K1 K7 K8 K10 K11 K13 K14 K16 K17 K19 K20 K22 K23 K25 K26 K28 K29 K31 K32 K34 K35 K37 K38 K40; MT1 1; MT2 1; MT3 1; MT4 1; MT5 1; MT6 1; MT7 1; MT8 1; U3 26(BDBUS0)* 27(BDBUS1)* 28(BDBUS2)* 29(BDBUS3)* 30(BDBUS4)* 32(BDBUS5)* 33(BDBUS6)* 34(BDBUS7)* 36(SUSPEND)* 48(DDBUS0)* 52(DDBUS1)* 53(DDBUS2)* 54(DDBUS3)* 55(DDBUS4)* 57(DDBUS5)* 58(DDBUS6)* 59(DDBUS7)* 60(PWREN)*; U4 7(NC)*; U6 2(NC1)* 4(6P4V2)* 5(6P4V1)* 6(3P2V)* 9(0P8V)* 17(NC2)* 18(NC3)* 19(NC4)*; U8 2(NC1)* 4(6P4V2)* 5(6P4V1)* 6(3P2V)* 9(0P8V)* 17(NC2)* 18(NC3)* 19(NC4)*; U10 1(NC1)* 3(NC3)*

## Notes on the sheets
sheet 8
- MATES W/ XILINX  FMC CONNECTOR - J22
- 12500 TI Boulevard. Dallas, Texas 75243
sheet 9
- 2A
- +5V_IN
- 12500 TI Boulevard. Dallas, Texas 75243
